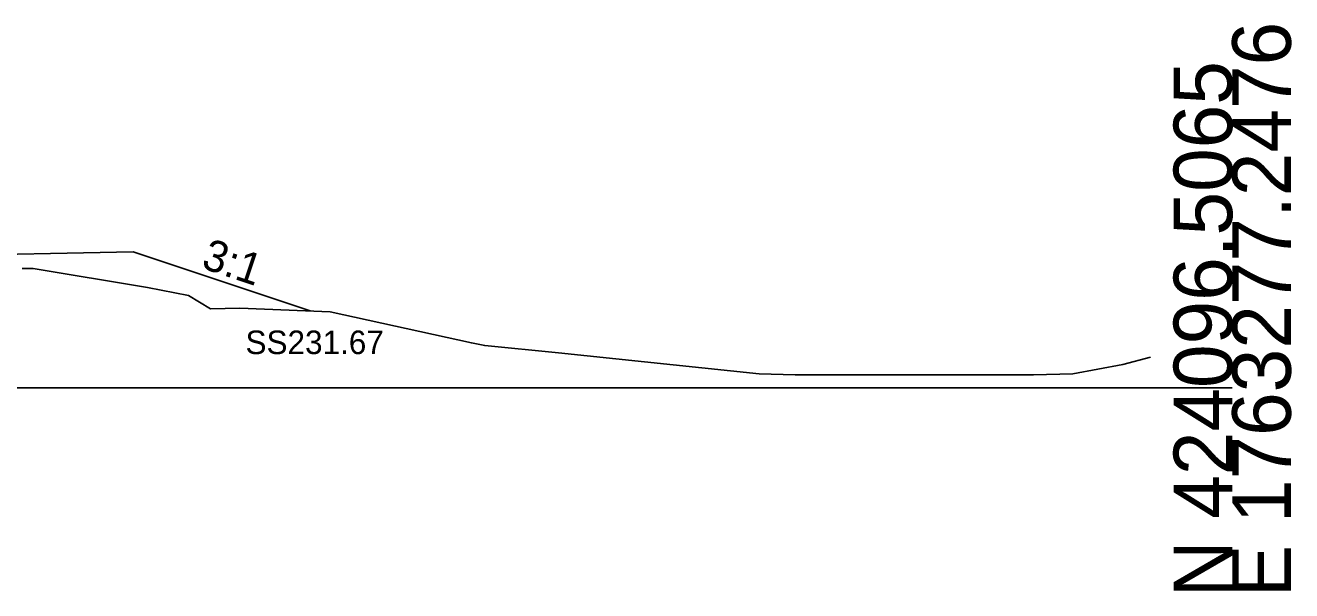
# Model space of a CAD drawing. Extents: x -26 to 3203, y -11010 to 4024.
# Drawn here: x 2142.3 to 2202.8, y -5009.7 to -4982.7 of the extents above; entities that cross this region are included whole.
import ezdxf

# ---------------------------------------------------------------- set-up
doc = ezdxf.new("R2010")
doc.units = 0
for name, color, linetype in [('Exist Cross Section Cell', 7, 'Continuous'), ('Exist XS Ground Line', 7, 'Continuous'), ('Prop CMT Slope Grass', 7, 'Continuous'), ('Prop XS Side Slope Text', 7, 'Continuous'), ('Prop XS SS Elevation Text', 7, 'Continuous'), ('Scratch_Level_0', 7, 'Continuous')]:
    doc.layers.add(name, color=color, linetype=linetype)

msp = doc.modelspace()

# ---------------------------------------------------------------- linework, layer by layer
at = {"layer": 'Exist Cross Section Cell'}
msp.add_line((2100, -5000), (2200, -5000), dxfattribs=at)
at = {"layer": 'Exist XS Ground Line'}
msp.add_lwpolyline([(2142.199, -4994.299), (2142.712, -4994.305), (2148.184, -4995.209), (2150.14, -4995.597), (2151.194, -4996.23), (2152.586, -4996.195), (2156.903, -4996.363), (2163.654, -4997.854), (2164.289, -4997.982), (2167.809, -4998.328), (2177.395, -4999.328), (2179.125, -4999.377), (2190.501, -4999.373), (2192.379, -4999.339), (2194.771, -4998.885), (2196.099, -4998.543)], dxfattribs=at)
msp.add_lwpolyline([(2142.199, -4994.299), (2142.712, -4994.305), (2148.184, -4995.209), (2150.14, -4995.597), (2151.194, -4996.23), (2152.586, -4996.195), (2156.903, -4996.363), (2163.654, -4997.854), (2164.289, -4997.982), (2167.809, -4998.328), (2177.395, -4999.328), (2179.125, -4999.377), (2190.501, -4999.373), (2192.379, -4999.339), (2194.771, -4998.885), (2196.099, -4998.543)], dxfattribs=at)
msp.add_lwpolyline([(2142.199, -4994.299), (2142.712, -4994.305), (2148.184, -4995.209), (2150.14, -4995.597), (2151.194, -4996.23), (2152.586, -4996.195), (2156.903, -4996.363), (2163.654, -4997.854), (2164.289, -4997.982), (2167.809, -4998.328), (2177.395, -4999.328), (2179.125, -4999.377), (2190.501, -4999.373), (2192.379, -4999.339), (2194.771, -4998.885), (2196.099, -4998.543)], dxfattribs=at)
msp.add_lwpolyline([(2142.199, -4994.299), (2142.712, -4994.305), (2148.184, -4995.209), (2150.14, -4995.597), (2151.194, -4996.23), (2152.586, -4996.195), (2156.903, -4996.363), (2163.654, -4997.854), (2164.289, -4997.982), (2167.809, -4998.328), (2177.395, -4999.328), (2179.125, -4999.377), (2190.501, -4999.373), (2192.379, -4999.339), (2194.771, -4998.885), (2196.099, -4998.543)], dxfattribs=at)
msp.add_lwpolyline([(2142.199, -4994.299), (2142.712, -4994.305), (2148.184, -4995.209), (2150.14, -4995.597), (2151.194, -4996.23), (2152.586, -4996.195), (2156.903, -4996.363), (2163.654, -4997.854), (2164.289, -4997.982), (2167.809, -4998.328), (2177.395, -4999.328), (2179.125, -4999.377), (2190.501, -4999.373), (2192.379, -4999.339), (2194.771, -4998.885), (2196.099, -4998.543)], dxfattribs=at)
at = {"layer": 'Prop CMT Slope Grass'}
msp.add_lwpolyline([(2138.001, -4993.699), (2147.501, -4993.509), (2155.954, -4996.326)], dxfattribs=at)

# ---------------------------------------------------------------- texts
at = {"layer": 'Exist Cross Section Cell'}
for s, p in [('E 1763277.2476', (2202.8, -5010)), ('N 424096.5065', (2200, -5010))]:
    msp.add_text(s, height=2.8, rotation=90, dxfattribs=at).set_placement(p)
at = {"layer": 'Prop XS Side Slope Text'}
msp.add_text('3:1', height=1.5, rotation=341.56507, dxfattribs=at).set_placement((2150.694, -4994.257))
at = {"layer": 'Prop XS SS Elevation Text'}
msp.add_text('SS231.67', height=1.125, dxfattribs=at).set_placement((2152.862, -4998.389))
at = {"layer": 'Scratch_Level_0'}
for s, p in [('RT_CSLP_Pnt', (2147.402, -4993.519)), ('Exterior Boundary', (2155.795, -4996.336)), ('RT_Slope_Fill', (2155.859, -4996.336))]:
    msp.add_text(s, height=0.02, dxfattribs=at).set_placement(p)

doc.saveas('drawing.dxf')
